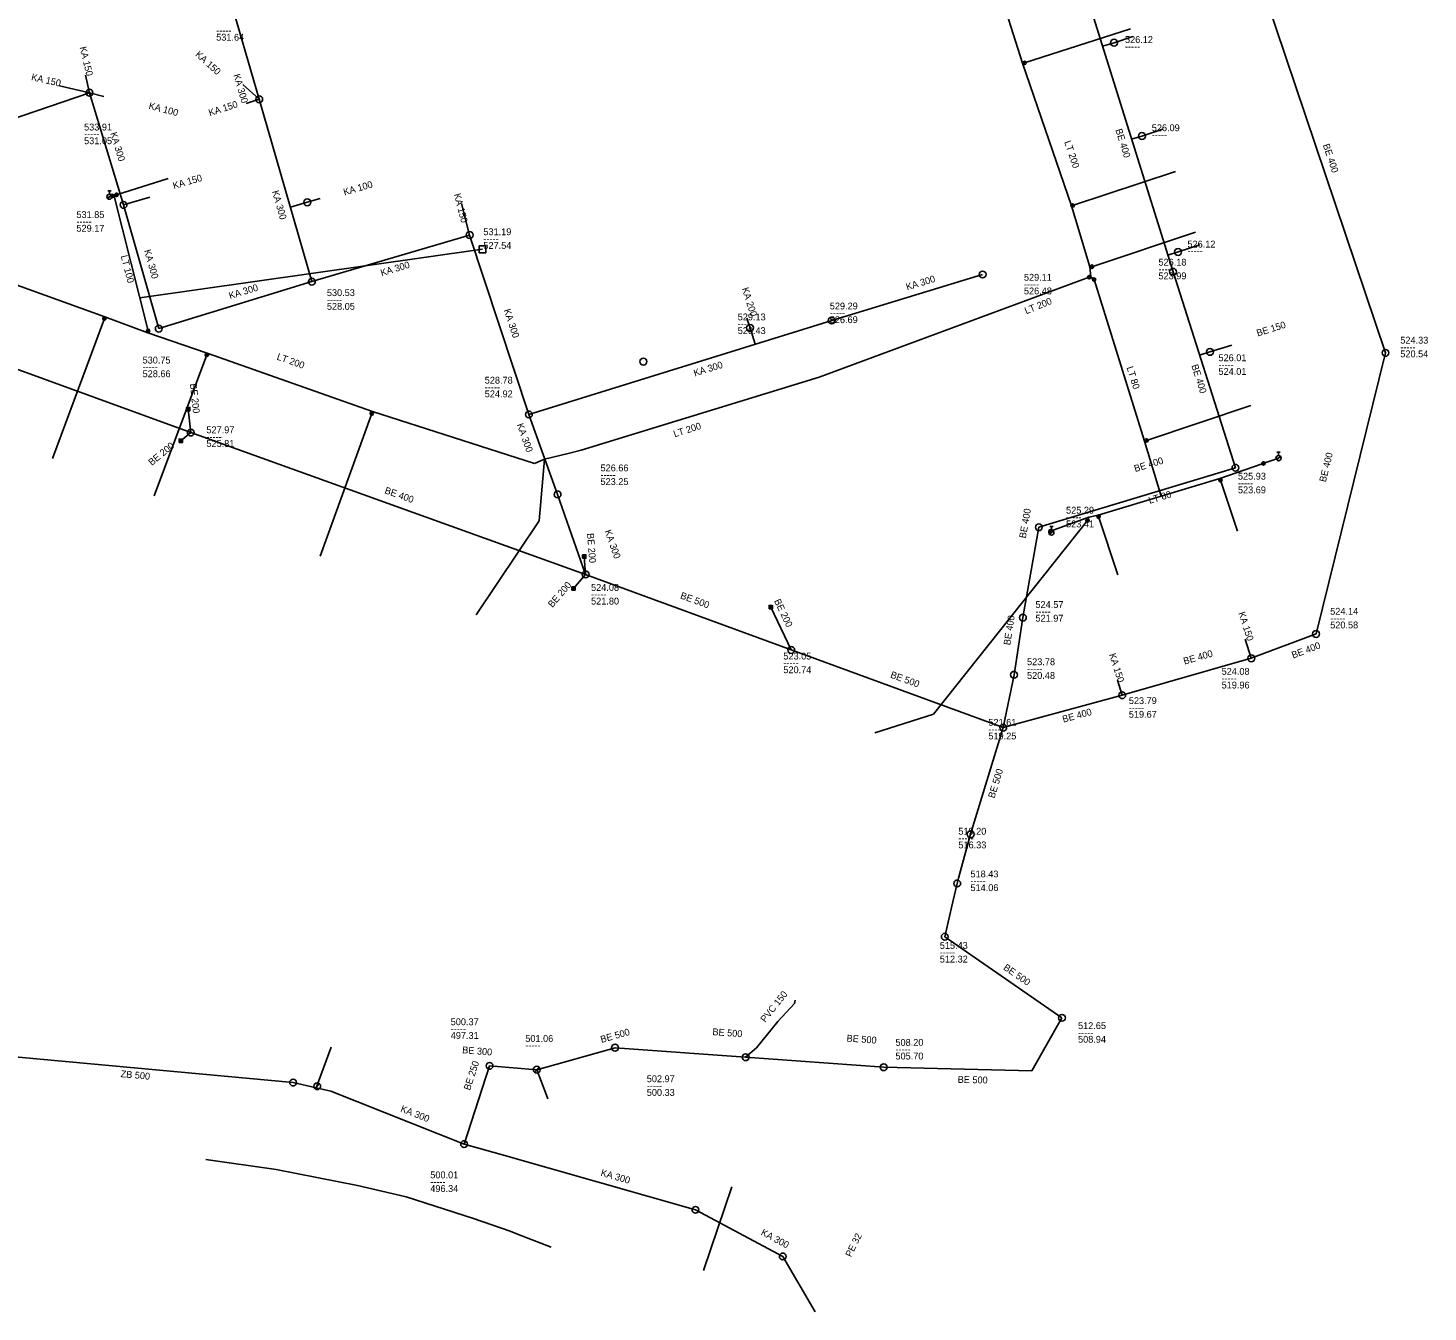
# Model space of a CAD drawing. Extents: x -769542 to -769122, y -1181691 to -1181360.
# Drawn here: x -769357.9 to -769153.1, y -1181691 to -1181503.2 of the extents above; entities that cross this region are included whole.
import ezdxf

# ---------------------------------------------------------------- set-up
doc = ezdxf.new("R2010")
doc.units = 0
for name, color, linetype in [('Level 19', 7, 'Continuous'), ('Level 20', 7, 'Continuous'), ('Level 21', 7, 'Continuous'), ('Level 24', 7, 'Continuous'), ('Level 26', 7, 'Continuous'), ('Level 29', 7, 'Continuous'), ('Level 40', 7, 'Continuous'), ('Level 41', 7, 'Continuous'), ('Level 44', 7, 'Continuous'), ('Level 45', 7, 'Continuous'), ('Level 46', 7, 'Continuous')]:
    doc.layers.add(name, color=color, linetype=linetype)

msp = doc.modelspace()

# ---------------------------------------------------------------- linework, layer by layer
at = {"layer": 'Level 19'}
for p, q in [((-769196.59, -1181503.37), (-769212.09, -1181508.34)), ((-769212.39, -1181508.39), (-769212.09, -1181508.34)), ((-769190.02, -1181524.21), (-769205.06, -1181529.2)), ((-769337.4, -1181525.25), (-769344.99, -1181527.63)), ((-769345.59, -1181527.8), (-769346.01, -1181527.91)), ((-769345.36, -1181527.64), (-769345.59, -1181527.8)), ((-769345.36, -1181527.64), (-769344.99, -1181527.63)), ((-769205.25, -1181529.25), (-769205.06, -1181529.2)), ((-769187.06, -1181533.1), (-769202.24, -1181538.14)), ((-769202.55, -1181538.15), (-769202.24, -1181538.14)), ((-769354.35, -1181566.17), (-769346.75, -1181545.71)), ((-769346.68, -1181545.48), (-769346.75, -1181545.71)), ((-769339.47, -1181571.63), (-769331.76, -1181551.02)), ((-769331.69, -1181550.81), (-769331.76, -1181551.02)), ((-769307.51, -1181559.3), (-769307.63, -1181559.62)), ((-769178.97, -1181558.45), (-769194.25, -1181563.55)), ((-769315.18, -1181580.47), (-769307.63, -1181559.62)), ((-769194.53, -1181563.67), (-769194.25, -1181563.55)), ((-769282.36, -1181566.29), (-769283.13, -1181575.29)), ((-769183.54, -1181569.12), (-769183.44, -1181569.37)), ((-769180.95, -1181576.81), (-769183.44, -1181569.37)), ((-769283.13, -1181575.29), (-769292.35, -1181589.05)), ((-769202.89, -1181575.24), (-769225.41, -1181603.59)), ((-769202.69, -1181574.76), (-769202.89, -1181575.24)), ((-769201.31, -1181574.49), (-769201.26, -1181574.7)), ((-769198.47, -1181583.22), (-769201.26, -1181574.7)), ((-769225.41, -1181603.59), (-769234.01, -1181606.3))]:
    msp.add_line(p, q, dxfattribs=at)
at = {"layer": 'Level 20'}
for p, q in [((-769218.94, -1181487.79), (-769212.39, -1181508.39)), ((-769212.39, -1181508.39), (-769205.25, -1181529.25)), ((-769340.36, -1181547.52), (-769345.36, -1181527.64)), ((-769205.25, -1181529.25), (-769202.55, -1181538.15)), ((-769374.78, -1181535.36), (-769346.68, -1181545.48)), ((-769291.42, -1181535.59), (-769341.58, -1181542.68)), ((-769202.39, -1181539.62), (-769202.55, -1181538.15)), ((-769242.16, -1181554.28), (-769202.62, -1181539.68)), ((-769202.62, -1181539.68), (-769202.39, -1181539.62)), ((-769202.39, -1181539.62), (-769201.92, -1181540.03)), ((-769201.92, -1181540.03), (-769194.53, -1181563.67)), ((-769346.68, -1181545.48), (-769340.39, -1181547.82)), ((-769340.39, -1181547.82), (-769340.36, -1181547.52)), ((-769340.39, -1181547.82), (-769331.69, -1181550.81)), ((-769331.69, -1181550.81), (-769307.51, -1181559.3)), ((-769276.96, -1181564.97), (-769242.16, -1181554.28)), ((-769307.51, -1181559.3), (-769283.83, -1181566.92)), ((-769282.36, -1181566.29), (-769278.9, -1181565.44)), ((-769278.9, -1181565.44), (-769276.96, -1181564.97)), ((-769192.1, -1181571.71), (-769194.53, -1181563.67)), ((-769283.83, -1181566.92), (-769282.36, -1181566.29)), ((-769174.93, -1181566.14), (-769183.54, -1181569.12)), ((-769183.54, -1181569.12), (-769201.31, -1181574.49)), ((-769202.69, -1181574.76), (-769208.3, -1181576.81)), ((-769201.31, -1181574.49), (-769202.69, -1181574.76)), ((-769208.3, -1181576.81), (-769208.17, -1181577.02)), ((-769321.61, -1181670.18), (-769331.9, -1181668.74)), ((-769309.71, -1181672.5), (-769321.61, -1181670.18)), ((-769302.58, -1181674.18), (-769309.71, -1181672.5)), ((-769302.58, -1181674.18), (-769292.75, -1181677.35)), ((-769292.75, -1181677.35), (-769287.38, -1181679.2)), ((-769287.38, -1181679.2), (-769286.28, -1181679.63)), ((-769286.28, -1181679.63), (-769281.38, -1181681.53))]:
    msp.add_line(p, q, dxfattribs=at)
at = {"layer": 'Level 21'}
for p, q in [((-769346.304, -1181528.141), (-769345.714, -1181527.678)), ((-769346.26, -1181527.035), (-769345.76, -1181527.035)), ((-769346.01, -1181527.535), (-769346.01, -1181527.035)), ((-769175.18, -1181565.265), (-769174.68, -1181565.265)), ((-769174.93, -1181565.765), (-769174.93, -1181565.265)), ((-769175.224, -1181566.371), (-769174.634, -1181565.908)), ((-769208.464, -1181577.251), (-769207.874, -1181576.788)), ((-769208.42, -1181576.145), (-769207.92, -1181576.145)), ((-769208.17, -1181576.645), (-769208.17, -1181576.145))]:
    msp.add_line(p, q, dxfattribs=at)
for centre in [(-769346.01, -1181527.91), (-769174.93, -1181566.14), (-769208.17, -1181577.02)]:
    msp.add_circle(centre, 0.375, dxfattribs=at)
at = {"layer": 'Level 26'}
for centre in [(-769212.09, -1181508.34), (-769345.59, -1181527.8), (-769344.99, -1181527.63), (-769205.06, -1181529.2), (-769202.24, -1181538.14), (-769202.62, -1181539.68), (-769201.92, -1181540.03), (-769346.75, -1181545.71), (-769340.36, -1181547.52), (-769331.76, -1181551.02), (-769307.63, -1181559.62), (-769194.25, -1181563.55), (-769177.14, -1181566.91), (-769183.44, -1181569.37), (-769202.89, -1181575.24), (-769201.26, -1181574.7), (-769208.3, -1181576.81)]:
    msp.add_circle(centre, 0.25, dxfattribs=at)
at = {"layer": 'Level 29'}
for p, q in [((-769290.92, -1181535.09), (-769291.92, -1181535.09)), ((-769291.92, -1181535.09), (-769291.92, -1181536.09)), ((-769291.92, -1181536.09), (-769290.92, -1181536.09)), ((-769290.92, -1181536.09), (-769290.92, -1181535.09))]:
    msp.add_line(p, q, dxfattribs=at)
at = {"layer": 'Level 40'}
for p, q in [((-769178.82, -1181492.7), (-769159.28, -1181550.75)), ((-769202.76, -1181499.32), (-769190.37, -1181538.88)), ((-769327.75, -1181501.05), (-769324.09, -1181513.66)), ((-769200.7, -1181505.91), (-769199, -1181505.38)), ((-769378.17, -1181522.7), (-769348.93, -1181512.7)), ((-769348.93, -1181512.7), (-769343.95, -1181529.1)), ((-769324.09, -1181513.66), (-769316.39, -1181540.33)), ((-769196.44, -1181519.51), (-769194.92, -1181519.03)), ((-769343.95, -1181529.1), (-769338.79, -1181547.2)), ((-769316.39, -1181540.33), (-769293.3, -1181533.51)), ((-769293.3, -1181533.51), (-769284.63, -1181559.75)), ((-769191.13, -1181536.46), (-769189.64, -1181535.99)), ((-769190.37, -1181538.88), (-769181.24, -1181567.55)), ((-769394.85, -1181540.3), (-769334.11, -1181562.4)), ((-769338.79, -1181547.2), (-769316.39, -1181540.33)), ((-769218.23, -1181539.28), (-769240.32, -1181546.01)), ((-769240.32, -1181546.01), (-769284.63, -1181559.75)), ((-769186.49, -1181551.07), (-769184.97, -1181550.6)), ((-769159.28, -1181550.75), (-769169.44, -1181591.85)), ((-769284.63, -1181559.75), (-769280.44, -1181571.44)), ((-769334.11, -1181562.4), (-769276.33, -1181583.15)), ((-769181.24, -1181567.55), (-769210.01, -1181576.25)), ((-769280.44, -1181571.44), (-769276.33, -1181583.15)), ((-769210.01, -1181576.25), (-769212.34, -1181589.46)), ((-769276.33, -1181583.15), (-769246.24, -1181594.19)), ((-769212.34, -1181589.46), (-769213.64, -1181597.83)), ((-769169.44, -1181591.85), (-769178.92, -1181595.41)), ((-769246.24, -1181594.19), (-769215.22, -1181605.56)), ((-769178.92, -1181595.41), (-769197.81, -1181600.81)), ((-769213.64, -1181597.83), (-769215.22, -1181605.56)), ((-769197.81, -1181600.81), (-769215.22, -1181605.56)), ((-769215.22, -1181605.56), (-769219.99, -1181621.15)), ((-769219.99, -1181621.15), (-769221.74, -1181627.56)), ((-769221.95, -1181628.34), (-769222.77, -1181631.86)), ((-769221.74, -1181627.56), (-769221.95, -1181628.34)), ((-769222.77, -1181631.86), (-769223.77, -1181636.14)), ((-769223.77, -1181636.14), (-769206.63, -1181648)), ((-769206.63, -1181648), (-769211.03, -1181655.74)), ((-769362.63, -1181653.44), (-769319.13, -1181657.46)), ((-769315.75, -1181658.22), (-769313.55, -1181652.28)), ((-769272.03, -1181652.37), (-769283.48, -1181655.58)), ((-769252.91, -1181653.76), (-769272.03, -1181652.37)), ((-769290.39, -1181655.03), (-769294.11, -1181666.47)), ((-769283.48, -1181655.58), (-769290.39, -1181655.03)), ((-769283.48, -1181655.58), (-769282.2, -1181658.94)), ((-769232.71, -1181655.22), (-769252.91, -1181653.76)), ((-769211.03, -1181655.74), (-769232.71, -1181655.22)), ((-769319.13, -1181657.46), (-769315.75, -1181658.22)), ((-769315.75, -1181658.22), (-769313.62, -1181658.7)), ((-769313.62, -1181658.7), (-769294.11, -1181666.47)), ((-769282.2, -1181658.94), (-769281.86, -1181659.84)), ((-769294.11, -1181666.47), (-769288.68, -1181668.01)), ((-769288.68, -1181668.01), (-769260.26, -1181676.08)), ((-769259.06, -1181684.94), (-769254.94, -1181672.73)), ((-769260.26, -1181676.08), (-769247.48, -1181682.9)), ((-769247.48, -1181682.9), (-769242.72, -1181691.02))]:
    msp.add_line(p, q, dxfattribs=at)
at = {"layer": 'Level 41'}
for p, q in [((-769283.824, -1181655.94), (-769283.121, -1181655.238)), ((-769315.954, -1181658.36), (-769315.251, -1181657.658))]:
    msp.add_line(p, q, dxfattribs=at)
for centre in [(-769199, -1181505.38), (-769348.93, -1181512.7), (-769324.09, -1181513.66), (-769194.92, -1181519.03), (-769343.95, -1181529.1), (-769317.06, -1181528.72), (-769293.3, -1181533.51), (-769189.64, -1181535.99), (-769218.23, -1181539.28), (-769190.37, -1181538.88), (-769316.39, -1181540.33), (-769338.79, -1181547.2), (-769252.27, -1181547.1), (-769240.32, -1181546.01), (-769184.97, -1181550.6), (-769159.28, -1181550.75), (-769267.88, -1181552.03), (-769284.63, -1181559.75), (-769284.63, -1181559.75), (-769334.11, -1181562.4), (-769181.24, -1181567.55), (-769280.44, -1181571.44), (-769210.01, -1181576.25), (-769276.33, -1181583.15), (-769212.34, -1181589.46), (-769212.34, -1181589.46), (-769169.44, -1181591.85), (-769246.24, -1181594.19), (-769178.92, -1181595.41), (-769213.64, -1181597.83), (-769213.64, -1181597.83), (-769197.81, -1181600.81), (-769215.22, -1181605.56), (-769219.99, -1181621.15), (-769219.99, -1181621.15), (-769221.95, -1181628.34), (-769223.77, -1181636.14), (-769223.77, -1181636.14), (-769206.63, -1181648), (-769206.63, -1181648), (-769272.03, -1181652.37), (-769272.03, -1181652.37), (-769252.91, -1181653.76), (-769290.39, -1181655.03), (-769290.39, -1181655.03), (-769283.48, -1181655.58), (-769283.48, -1181655.58), (-769232.71, -1181655.22), (-769232.71, -1181655.22), (-769319.13, -1181657.46), (-769315.61, -1181658), (-769294.11, -1181666.47), (-769294.11, -1181666.47), (-769260.26, -1181676.08), (-769247.48, -1181682.9)]:
    msp.add_circle(centre, 0.5, dxfattribs=at)
at = {"layer": 'Level 45'}
for p, q in [((-769196.23, -1181504.49), (-769199, -1181505.38)), ((-769349.53, -1181510.15), (-769348.93, -1181512.7)), ((-769353.33, -1181511.7), (-769348.93, -1181512.7)), ((-769326.48, -1181511.49), (-769324.09, -1181513.66)), ((-769346.82, -1181513.25), (-769348.93, -1181512.7)), ((-769326.02, -1181514.28), (-769324.09, -1181513.66)), ((-769191.86, -1181518.05), (-769194.92, -1181519.03)), ((-769340.09, -1181527.97), (-769343.95, -1181529.1)), ((-769317.06, -1181528.72), (-769319.54, -1181529.43)), ((-769315.16, -1181528.17), (-769317.06, -1181528.72)), ((-769294.49, -1181528.9), (-769293.3, -1181533.51)), ((-769186.46, -1181534.93), (-769189.64, -1181535.99)), ((-769252.72, -1181545.69), (-769252.27, -1181547.1)), ((-769252.27, -1181547.1), (-769251.51, -1181549.48)), ((-769181.77, -1181549.6), (-769184.97, -1181550.6)), ((-769334.48, -1181558.97), (-769334.11, -1181562.4)), ((-769335.56, -1181563.6), (-769334.11, -1181562.4)), ((-769276.53, -1181580.53), (-769276.33, -1181583.15)), ((-769278.11, -1181585.22), (-769276.33, -1181583.15)), ((-769249.24, -1181587.94), (-769246.24, -1181594.19)), ((-769179.8, -1181592.64), (-769178.92, -1181595.41)), ((-769198.51, -1181598.6), (-769197.81, -1181600.81)), ((-769245.67, -1181645.42), (-769245.77, -1181645.9)), ((-769245.77, -1181645.9), (-769248.2, -1181648.52)), ((-769248.2, -1181648.52), (-769251.31, -1181652.38)), ((-769251.31, -1181652.38), (-769252.91, -1181653.76))]:
    msp.add_line(p, q, dxfattribs=at)
at = {"layer": 'Level 46'}
for p, q in [((-769334.73, -1181558.97), (-769334.23, -1181558.97)), ((-769335.81, -1181563.6), (-769335.31, -1181563.6)), ((-769276.78, -1181580.53), (-769276.28, -1181580.53)), ((-769278.36, -1181585.22), (-769277.86, -1181585.22)), ((-769249.49, -1181587.94), (-769248.99, -1181587.94))]:
    msp.add_line(p, q, dxfattribs=at)
for points in [[(-769334.73, -1181559.221), (-769334.2295, -1181559.221), (-769334.2295, -1181558.7195), (-769334.73, -1181558.7195)], [(-769335.81, -1181563.851), (-769335.3095, -1181563.851), (-769335.3095, -1181563.3495), (-769335.81, -1181563.3495)], [(-769276.78, -1181580.781), (-769276.2795, -1181580.781), (-769276.2795, -1181580.2795), (-769276.78, -1181580.2795)], [(-769278.36, -1181585.471), (-769277.8595, -1181585.471), (-769277.8595, -1181584.9695), (-769278.36, -1181584.9695)], [(-769249.49, -1181588.191), (-769248.9895, -1181588.191), (-769248.9895, -1181587.6895), (-769249.49, -1181587.6895)]]:
    msp.add_lwpolyline(points, close=True, dxfattribs=at)

# ---------------------------------------------------------------- texts
at = {"layer": 'Level 24'}
for s, rotation, p in [('LT 200', 288.895, (-769206.31, -1181519.9)), ('LT 100', 284.118, (-769344.36, -1181536.58)), ('LT 200', 22.23, (-769211.85, -1181545.11)), ('LT 200', 340.471, (-769321.61, -1181551.7)), ('LT 80', 287.36, (-769197.18, -1181552.88)), ('LT 200', 17.692, (-769263.3, -1181563.1)), ('LT 80', 16.815, (-769193.79, -1181572.83)), ('PE 32', 63.783, (-769237.48, -1181683.07))]:
    msp.add_text(s, height=1, rotation=rotation, dxfattribs=at).set_placement(p)
at = {"layer": 'Level 44'}
for s, p in [('531.64', (-769330.39, -1181505.08)), ('-----', (-769330.39, -1181504.08)), ('526.12', (-769197.4, -1181505.42)), ('-----', (-769197.4, -1181506.42)), ('533.91', (-769349.72, -1181518.22)), ('526.09', (-769193.48, -1181518.32)), ('531.05', (-769349.72, -1181520.22)), ('-----', (-769349.72, -1181519.22)), ('-----', (-769193.48, -1181519.32)), ('531.85', (-769350.84, -1181531.02)), ('529.17', (-769350.84, -1181533.02)), ('-----', (-769350.84, -1181532.02)), ('531.19', (-769291.29, -1181533.53)), ('527.54', (-769291.29, -1181535.53)), ('-----', (-769291.29, -1181534.53)), ('526.12', (-769188.26, -1181535.34)), ('526.18', (-769192.5, -1181537.98)), ('-----', (-769188.26, -1181536.34)), ('523.99', (-769192.5, -1181539.98)), ('-----', (-769192.5, -1181538.98)), ('529.11', (-769212.19, -1181540.19)), ('-----', (-769212.19, -1181541.19)), ('530.53', (-769314.19, -1181542.44)), ('-----', (-769314.19, -1181543.44)), ('526.48', (-769212.19, -1181542.19)), ('528.05', (-769314.19, -1181544.44)), ('529.13', (-769254.07, -1181545.99)), ('529.29', (-769240.6, -1181544.39)), ('-----', (-769240.6, -1181545.39)), ('526.43', (-769254.07, -1181547.99)), ('-----', (-769254.07, -1181546.99)), ('526.69', (-769240.6, -1181546.39)), ('524.33', (-769157.11, -1181549.39)), ('530.75', (-769341.16, -1181552.3)), ('526.01', (-769183.72, -1181551.96)), ('520.54', (-769157.11, -1181551.39)), ('-----', (-769157.11, -1181550.39)), ('528.66', (-769341.16, -1181554.3)), ('-----', (-769341.16, -1181553.3)), ('524.01', (-769183.72, -1181553.96)), ('-----', (-769183.72, -1181552.96)), ('528.78', (-769291.09, -1181555.24)), ('524.92', (-769291.09, -1181557.24)), ('-----', (-769291.09, -1181556.24)), ('527.97', (-769331.82, -1181562.5)), ('525.81', (-769331.82, -1181564.5)), ('-----', (-769331.82, -1181563.5)), ('526.66', (-769274.15, -1181568.07)), ('523.25', (-769274.15, -1181570.07)), ('-----', (-769274.15, -1181569.07)), ('525.93', (-769180.87, -1181569.28)), ('523.69', (-769180.87, -1181571.28)), ('-----', (-769180.87, -1181570.28)), ('525.29', (-769206.02, -1181574.26)), ('523.41', (-769206.02, -1181576.26)), ('-----', (-769206.02, -1181575.26)), ('524.08', (-769275.53, -1181585.55)), ('-----', (-769275.53, -1181586.55)), ('521.80', (-769275.53, -1181587.55)), ('524.57', (-769210.5, -1181588.05)), ('524.14', (-769167.37, -1181589.04)), ('521.97', (-769210.5, -1181590.05)), ('-----', (-769210.5, -1181589.05)), ('520.58', (-769167.37, -1181591.04)), ('-----', (-769167.37, -1181590.04)), ('523.05', (-769247.39, -1181595.59)), ('-----', (-769247.39, -1181596.59)), ('523.78', (-769211.73, -1181596.42)), ('520.74', (-769247.39, -1181597.59)), ('520.48', (-769211.73, -1181598.42)), ('-----', (-769211.73, -1181597.42)), ('524.08', (-769183.26, -1181597.83)), ('-----', (-769183.26, -1181598.83)), ('519.96', (-769183.26, -1181599.83)), ('523.79', (-769196.84, -1181602.11)), ('521.61', (-769217.39, -1181605.28)), ('519.67', (-769196.84, -1181604.11)), ('-----', (-769196.84, -1181603.11)), ('519.25', (-769217.39, -1181607.28)), ('-----', (-769217.39, -1181606.28)), ('519.20', (-769221.78, -1181621.21)), ('516.33', (-769221.78, -1181623.21)), ('-----', (-769221.78, -1181622.21)), ('518.43', (-769220.01, -1181627.46)), ('514.06', (-769220.01, -1181629.46)), ('-----', (-769220.01, -1181628.46)), ('515.43', (-769224.5, -1181637.91)), ('512.32', (-769224.5, -1181639.91)), ('-----', (-769224.5, -1181638.91)), ('500.37', (-769296.07, -1181649.08)), ('-----', (-769296.07, -1181650.08)), ('512.65', (-769204.27, -1181649.64)), ('497.31', (-769296.07, -1181651.08)), ('501.06', (-769285.16, -1181651.52)), ('508.20', (-769230.99, -1181652.09)), ('508.94', (-769204.27, -1181651.64)), ('-----', (-769204.27, -1181650.64)), ('-----', (-769285.16, -1181652.52)), ('505.70', (-769230.99, -1181654.09)), ('-----', (-769230.99, -1181653.09)), ('502.97', (-769267.38, -1181657.41)), ('500.33', (-769267.38, -1181659.41)), ('-----', (-769267.38, -1181658.41)), ('500.01', (-769299.06, -1181671.47)), ('-----', (-769299.06, -1181672.47)), ('496.34', (-769299.06, -1181673.47))]:
    msp.add_text(s, height=1, dxfattribs=at).set_placement(p)
for s, rotation, p in [('KA 150', 283.319, (-769350.38, -1181506.06)), ('KA 150', 317.896, (-769333.53, -1181507.23)), ('KA 150', 347.212, (-769357.52, -1181510.85)), ('KA 300', 286.205, (-769327.88, -1181510.1)), ('KA 100', 345.338, (-769340.34, -1181515.03)), ('KA 150', 17.766, (-769331.32, -1181516.13)), ('KA 300', 286.891, (-769345.91, -1181518.63)), ('BE 400', 287.39, (-769198.82, -1181518.13)), ('BE 400', 288.604, (-769168.46, -1181520.35)), ('KA 150', 16.368, (-769336.57, -1181526.8)), ('KA 100', 16.001, (-769311.62, -1181527.73)), ('KA 300', 286.095, (-769322.23, -1181527.14)), ('KA 150', 284.524, (-769295.62, -1181527.56)), ('KA 300', 285.912, (-769340.96, -1181535.78)), ('KA 300', 17.051, (-769306.17, -1181539.55)), ('KA 300', 17.051, (-769328.36, -1181542.89)), ('KA 300', 16.944, (-769229.27, -1181541.61)), ('KA 200', 287.706, (-769253.48, -1181541.35)), ('KA 300', 288.284, (-769288.32, -1181544.5)), ('BE 150', 17.354, (-769177.97, -1181548.35)), ('KA 300', 17.228, (-769260.35, -1181554.2)), ('BE 400', 287.664, (-769187.7, -1181552.6)), ('BE 200', 276.157, (-769334.24, -1181555.27)), ('KA 300', 289.719, (-769286.42, -1181561.25)), ('BE 200', 39.611, (-769339.81, -1181567.29)), ('BE 400', 76.115, (-769168.02, -1181569.71)), ('BE 400', 16.825, (-769195.9, -1181568.18)), ('BE 400', 340.246, (-769305.83, -1181571.25)), ('BE 400', 79.997, (-769211.92, -1181577.92)), ('BE 200', 274.365, (-769276.12, -1181577.14)), ('KA 300', 289.34, (-769273.56, -1181576.81)), ('BE 200', 49.308, (-769281.19, -1181588.07)), ('BE 500', 339.852, (-769262.56, -1181586.63)), ('BE 200', 295.641, (-769248.78, -1181587.02)), ('BE 400', 81.172, (-769214.2, -1181593.55)), ('KA 150', 287.625, (-769180.82, -1181588.79)), ('BE 400', 15.953, (-769188.69, -1181596.34)), ('BE 400', 20.583, (-769172.8, -1181595.46)), ('KA 150', 287.575, (-769199.74, -1181594.86)), ('BE 500', 339.87, (-769231.82, -1181598.21)), ('BE 400', 15.261, (-769206.41, -1181604.83)), ('BE 500', 72.988, (-769216.51, -1181615.95)), ('BE 500', 325.319, (-769215.29, -1181640.86)), ('PVC 150', 51.311, (-769250.06, -1181648.75)), ('BE 500', 15.661, (-769274, -1181651.67)), ('BE 500', 355.842, (-769257.8, -1181650.52)), ('BE 500', 355.866, (-769238.16, -1181651.46)), ('BE 300', 355.449, (-769294.42, -1181653.17)), ('ZB 500', 354.72, (-769344.41, -1181656.66)), ('BE 250', 71.987, (-769293.25, -1181658.67)), ('BE 500', 358.626, (-769221.89, -1181657.5)), ('KA 300', 338.285, (-769303.5, -1181661.66)), ('KA 300', 344.148, (-769274.2, -1181671.08)), ('KA 300', 331.914, (-769250.77, -1181679.69))]:
    msp.add_text(s, height=1, rotation=rotation, dxfattribs=at).set_placement(p)

doc.saveas('drawing.dxf')
